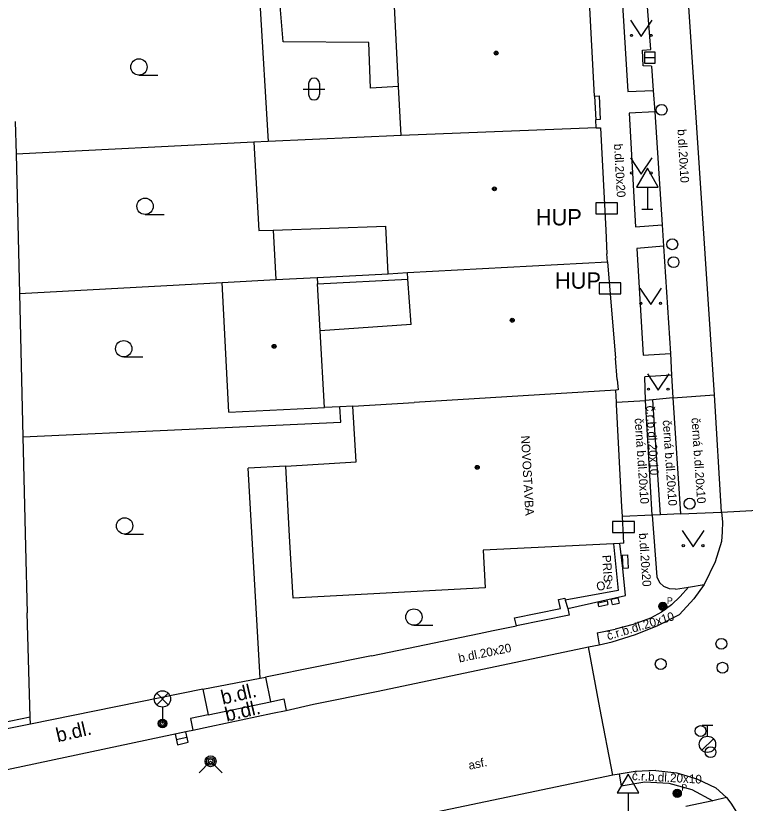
# Model space of a CAD drawing. Extents: x -596229 to -595156, y -1161237 to -1159376.
# Drawn here: x -595654.4 to -595620.89, y -1160970.18 to -1160933.99 of the extents above; entities that cross this region are included whole.
import ezdxf

# ---------------------------------------------------------------- set-up
doc = ezdxf.new("R2010")
doc.units = 0
for name, color, linetype in [('DOP - kresba z DSPS bez souradnic', 7, 'Continuous'), ('DOP - rozhrani ploch obecne', 7, 'Continuous'), ('Level 24', 7, 'Continuous'), ('Level 27', 7, 'Continuous'), ('Level 28', 7, 'Continuous'), ('Level 31', 7, 'Continuous'), ('Level 33', 7, 'Continuous'), ('Level 34', 7, 'Continuous'), ('Level 36', 7, 'Continuous'), ('Level 39', 7, 'Continuous'), ('silnoproud - povrch.  znaky a  RIS  skut. velikost', 7, 'Continuous'), ('slaboproud - povrch.  znaky a tel. budka skut. velikost', 7, 'Continuous'), ('TM - budovy zdene_ betonove - VP', 7, 'Continuous'), ('TM - chodniky - VP', 7, 'Continuous'), ('TM - komunikace - VP', 7, 'Continuous'), ('TM - letecke snimky - pomocna linie', 7, 'Continuous'), ('TM - plot drateny_ kovovy - VP', 7, 'Continuous'), ('TM - plot zdeny_ ohradni zed - VP', 7, 'Continuous'), ('TM - podezdivka plotu - VP', 7, 'Continuous'), ('TM - popis objektu', 7, 'Continuous'), ('TM - popis povrchu', 7, 'Continuous'), ('TM - rozhrani mezi zpev. plochami mezi sebou - VP', 7, 'Continuous'), ('TM - rozhrani ploch obecne - VP', 7, 'Continuous'), ('TM - vjezd na pozemek', 7, 'Continuous'), ('TM - vstup do budovy - zdene_ betonove', 7, 'Continuous'), ('Vrstva 34', 7, 'Continuous')]:
    doc.layers.add(name, color=color, linetype=linetype)

msp = doc.modelspace()

# ---------------------------------------------------------------- linework, layer by layer
at = {"layer": 'DOP - kresba z DSPS bez souradnic'}
for points in [[(-595642.11, -1160935.19), (-595642.27, -1160933.34)], [(-595638.18, -1160935.21), (-595642.11, -1160935.19)], [(-595638.1, -1160937.31), (-595638.18, -1160935.21)], [(-595636.82, -1160937.24), (-595638.1, -1160937.31)], [(-595640.53, -1160946.31), (-595636.38, -1160946.09)]]:
    msp.add_lwpolyline(points, dxfattribs=at)
at = {"layer": 'DOP - rozhrani ploch obecne'}
for points in [[(-595643.18, -1160933.39), (-595642.81, -1160939.77)], [(-595654.42, -1160938.84), (-595654.38, -1160940.34)], [(-595643.46, -1160939.8), (-595654.38, -1160940.34)], [(-595654.38, -1160940.34), (-595654.23, -1160946.75)], [(-595642.58, -1160943.84), (-595642.45, -1160946.11)], [(-595640.55, -1160946.01), (-595637.29, -1160945.84)], [(-595654.23, -1160946.75), (-595644.91, -1160946.24)], [(-595654.23, -1160946.75), (-595654.07, -1160953.34)], [(-595639.47, -1160952.66), (-595639.51, -1160951.96)], [(-595654.07, -1160953.34), (-595639.47, -1160952.66)], [(-595654.07, -1160953.34), (-595653.95, -1160958.4)], [(-595653.95, -1160958.4), (-595653.87, -1160961.43)]]:
    msp.add_lwpolyline(points, dxfattribs=at)
at = {"layer": 'Level 24'}
for points in [[(-595627.748, -1160943.089), (-595626.748, -1160943.089), (-595626.748, -1160942.589), (-595627.748, -1160942.589)], [(-595627.598, -1160946.759), (-595626.598, -1160946.759), (-595626.598, -1160946.259), (-595627.598, -1160946.259)], [(-595626.978, -1160957.729), (-595625.978, -1160957.729), (-595625.978, -1160957.229), (-595626.978, -1160957.229)]]:
    msp.add_lwpolyline(points, close=True, dxfattribs=at)
at = {"layer": 'Level 27'}
for p, q in [((-595625.52, -1160935.91), (-595625.02, -1160935.91)), ((-595647.024, -1160967.246), (-595646.536, -1160967.134))]:
    msp.add_line(p, q, dxfattribs=at)
for points in [[(-595625.52, -1160936.16), (-595625.02, -1160936.16), (-595625.02, -1160935.66), (-595625.52, -1160935.66)], [(-595646.967, -1160967.49), (-595646.48, -1160967.377), (-595646.593, -1160966.89), (-595647.08, -1160967.003)]]:
    msp.add_lwpolyline(points, close=True, dxfattribs=at)
at = {"layer": 'Level 28'}
for p, q in [((-595622.87, -1160966.595), (-595622.37, -1160966.595)), ((-595622.62, -1160967.095), (-595622.62, -1160966.595)), ((-595622.878, -1160967.742), (-595622.348, -1160967.212))]:
    msp.add_line(p, q, dxfattribs=at)
for centre, radius in [((-595624.73, -1160938.31), 0.25), ((-595624.24, -1160944.49), 0.25), ((-595624.18, -1160945.31), 0.25), ((-595623.44, -1160956.41), 0.25), ((-595622.94, -1160966.86), 0.25), ((-595622.62, -1160967.47), 0.375), ((-595622.48, -1160967.83), 0.25)]:
    msp.add_circle(centre, radius, dxfattribs=at)
at = {"layer": 'Level 31'}
msp.add_lwpolyline([(-595645.98, -1160968.78), (-595645.45, -1160968.25), (-595644.92, -1160968.78)], dxfattribs=at)
for centre, radius in [((-595621.98, -1160962.85), 0.25), ((-595624.77, -1160963.78), 0.25), ((-595621.93, -1160963.95), 0.25), ((-595645.45, -1160968.25), 0.25), ((-595645.45, -1160968.25), 0.18), ((-595645.45, -1160968.25), 0.11)]:
    msp.add_circle(centre, radius, dxfattribs=at)
at = {"layer": 'Level 33'}
for p, q in [((-595647.925, -1160965.65), (-595647.395, -1160965.12)), ((-595647.925, -1160965.12), (-595647.395, -1160965.65)), ((-595647.66, -1160965.76), (-595647.66, -1160966.51))]:
    msp.add_line(p, q, dxfattribs=at)
for centre, radius in [((-595647.66, -1160965.385), 0.375), ((-595647.66, -1160966.51), 0.2), ((-595647.66, -1160966.51), 0.145), ((-595647.66, -1160966.51), 0.0876)]:
    msp.add_circle(centre, radius, dxfattribs=at)
at = {"layer": 'Level 34'}
for p, q in [((-595625.38, -1160941.862), (-595625.38, -1160942.88)), ((-595625.63, -1160942.88), (-595625.13, -1160942.88)), ((-595626.27, -1160969.702), (-595626.27, -1160970.72))]:
    msp.add_line(p, q, dxfattribs=at)
for points in [[(-595625.88, -1160941.862), (-595624.88, -1160941.862), (-595625.38, -1160940.996)], [(-595626.77, -1160969.702), (-595625.77, -1160969.702), (-595626.27, -1160968.836)]]:
    msp.add_lwpolyline(points, close=True, dxfattribs=at)
at = {"layer": 'Level 36'}
for p, q in [((-595648.74, -1160936.715), (-595647.865, -1160936.715)), ((-595641.196, -1160937.356), (-595640.196, -1160937.356)), ((-595640.946, -1160937.106), (-595640.946, -1160937.606)), ((-595640.446, -1160937.106), (-595640.446, -1160937.606)), ((-595648.46, -1160943.115), (-595647.585, -1160943.115)), ((-595649.44, -1160949.665), (-595648.565, -1160949.665)), ((-595649.4, -1160957.805), (-595648.525, -1160957.805)), ((-595636.11, -1160961.995), (-595635.235, -1160961.995))]:
    msp.add_line(p, q, dxfattribs=at)
for points in [[(-595626.16, -1160934.19), (-595625.66, -1160934.94), (-595625.16, -1160934.19)], [(-595626.16, -1160940.51), (-595625.66, -1160941.26), (-595625.16, -1160940.51)], [(-595625.73, -1160946.5), (-595625.23, -1160947.25), (-595624.73, -1160946.5)], [(-595625.38, -1160950.45), (-595624.88, -1160951.2), (-595624.38, -1160950.45)], [(-595623.78, -1160957.64), (-595623.28, -1160958.39), (-595622.78, -1160957.64)]]:
    msp.add_lwpolyline(points, dxfattribs=at)
for centre, radius in [((-595626.11, -1160934.89), 0.05), ((-595625.211, -1160934.89), 0.05), ((-595648.74, -1160936.34), 0.375), ((-595626.11, -1160941.21), 0.05), ((-595625.211, -1160941.21), 0.05), ((-595648.46, -1160942.74), 0.375), ((-595625.68, -1160947.2), 0.05), ((-595624.781, -1160947.2), 0.05), ((-595649.44, -1160949.29), 0.375), ((-595625.33, -1160951.15), 0.05), ((-595624.431, -1160951.15), 0.05), ((-595649.4, -1160957.43), 0.375), ((-595623.73, -1160958.34), 0.05), ((-595622.831, -1160958.34), 0.05), ((-595636.11, -1160961.62), 0.375)]:
    msp.add_circle(centre, radius, dxfattribs=at)
for centre, start, end in [((-595640.696, -1160937.106), 0, 180), ((-595640.696, -1160937.606), 180, 0)]:
    msp.add_arc(centre, 0.25, start, end, dxfattribs=at)
at = {"layer": 'Level 39'}
for centre, radius in [((-595632.33, -1160935.7), 0.09), ((-595632.33, -1160935.7), 0.0398), ((-595632.41, -1160941.94), 0.09), ((-595632.41, -1160941.94), 0.0398), ((-595631.59, -1160947.98), 0.09), ((-595631.59, -1160947.98), 0.0398), ((-595642.53, -1160949.18), 0.09), ((-595642.53, -1160949.18), 0.0398), ((-595633.2, -1160954.74), 0.09), ((-595633.2, -1160954.74), 0.0398)]:
    msp.add_circle(centre, radius, dxfattribs=at)
at = {"layer": 'silnoproud - povrch.  znaky a  RIS  skut. velikost'}
for points in [[(-595626.54, -1160958.77), (-595626.29, -1160958.76)], [(-595626.29, -1160958.76), (-595626.26, -1160959.38)], [(-595626.54, -1160958.77), (-595626.51, -1160959.39)], [(-595626.26, -1160959.38), (-595626.51, -1160959.39)]]:
    msp.add_lwpolyline(points, dxfattribs=at)
at = {"layer": 'slaboproud - povrch.  znaky a tel. budka skut. velikost'}
for points in [[(-595627.65, -1160960.96), (-595627.23, -1160960.87)], [(-595627.23, -1160960.87), (-595627.2, -1160961.04)], [(-595627.04, -1160960.8), (-595626.74, -1160960.74)], [(-595626.98, -1160961.05), (-595627.04, -1160960.8)], [(-595626.74, -1160960.74), (-595626.68, -1160960.99)], [(-595627.61, -1160961.13), (-595627.65, -1160960.96)], [(-595627.61, -1160961.13), (-595627.2, -1160961.04)], [(-595626.98, -1160961.05), (-595626.68, -1160960.99)]]:
    msp.add_lwpolyline(points, dxfattribs=at)
at = {"layer": 'TM - budovy zdene_ betonove - VP'}
for points in [[(-595627.81, -1160937.68), (-595628.05, -1160933.02)], [(-595636.82, -1160937.24), (-595637.02, -1160933.22)], [(-595636.7, -1160939.49), (-595636.82, -1160937.24)], [(-595627.73, -1160939.14), (-595627.75, -1160938.77)], [(-595627.73, -1160939.14), (-595636.7, -1160939.49)], [(-595627.73, -1160939.14), (-595627.54, -1160939.13), (-595627.29, -1160943.84)], [(-595636.7, -1160939.49), (-595642.81, -1160939.77)], [(-595642.81, -1160939.77), (-595643.46, -1160939.8)], [(-595637.29, -1160945.84), (-595637.4, -1160943.66)], [(-595627.22, -1160945.3), (-595627.24, -1160944.92)], [(-595636.4, -1160945.79), (-595627.22, -1160945.3)], [(-595627.22, -1160945.3), (-595626.85, -1160949.72)], [(-595642.45, -1160946.11), (-595640.55, -1160946.01)], [(-595640.55, -1160946.01), (-595640.53, -1160946.31)], [(-595637.29, -1160945.84), (-595636.4, -1160945.79)], [(-595636.38, -1160946.09), (-595636.4, -1160945.79)], [(-595636.24, -1160948.18), (-595636.38, -1160946.09)], [(-595644.91, -1160946.24), (-595642.45, -1160946.11)], [(-595644.61, -1160952.21), (-595644.91, -1160946.24)], [(-595640.41, -1160948.46), (-595640.53, -1160946.31)], [(-595636.24, -1160948.18), (-595640.41, -1160948.46)], [(-595640.21, -1160951.99), (-595640.41, -1160948.46)], [(-595626.77, -1160950.7), (-595626.73, -1160951.18), (-595626.83, -1160951.19)], [(-595626.83, -1160951.19), (-595636.09, -1160951.76)], [(-595626.8, -1160951.74), (-595626.83, -1160951.19)], [(-595638.92, -1160951.93), (-595636.09, -1160951.76)], [(-595626.8, -1160951.85), (-595626.8, -1160951.74)], [(-595644.61, -1160952.21), (-595640.21, -1160951.99)], [(-595639.51, -1160951.96), (-595640.21, -1160951.99)], [(-595638.92, -1160951.93), (-595639.51, -1160951.96)], [(-595638.76, -1160954.49), (-595638.92, -1160951.93)], [(-595641.99, -1160954.68), (-595638.76, -1160954.49)], [(-595641.82, -1160957.9), (-595641.99, -1160954.68)], [(-595626.53, -1160957), (-595626.55, -1160956.56)], [(-595626.46, -1160958.23), (-595626.53, -1160957)], [(-595641.66, -1160960.75), (-595641.82, -1160957.9)], [(-595626.94, -1160958.25), (-595632.93, -1160958.55)], [(-595626.64, -1160958.24), (-595626.94, -1160958.25)], [(-595626.46, -1160958.23), (-595626.64, -1160958.24)], [(-595632.93, -1160958.55), (-595632.83, -1160960.28)], [(-595632.83, -1160960.28), (-595641.66, -1160960.75)]]:
    msp.add_lwpolyline(points, dxfattribs=at)
at = {"layer": 'TM - chodniky - VP'}
for points in [[(-595626.58, -1160932.48), (-595626.28, -1160937.46)], [(-595626.28, -1160937.46), (-595625.11, -1160937.42)], [(-595625.04, -1160938.4), (-595626.22, -1160938.46)], [(-595626.22, -1160938.46), (-595625.92, -1160943.69)], [(-595625.92, -1160943.69), (-595624.7, -1160943.6)], [(-595624.64, -1160944.58), (-595625.87, -1160944.68)], [(-595625.87, -1160944.68), (-595625.58, -1160949.59)], [(-595625.58, -1160949.59), (-595624.32, -1160949.51)], [(-595624.27, -1160950.51), (-595625.5, -1160950.58)], [(-595625.47, -1160951.67), (-595625.5, -1160950.58)], [(-595625.13, -1160951.63), (-595625.47, -1160951.67)], [(-595624.21, -1160951.54), (-595625.13, -1160951.63)], [(-595624.78, -1160956.92), (-595625.16, -1160956.94)], [(-595625.16, -1160956.94), (-595624.95, -1160959.77)], [(-595623.86, -1160956.87), (-595624.78, -1160956.92)], [(-595623.86, -1160956.87), (-595621.97, -1160956.8)], [(-595624.95, -1160959.77), (-595624.83, -1160960.03)], [(-595624.83, -1160960.03), (-595624.63, -1160960.22)], [(-595623.49, -1160960.25), (-595622.78, -1160960.13)], [(-595624.09, -1160960.34), (-595624.37, -1160960.33), (-595624.63, -1160960.22)], [(-595624.09, -1160960.34), (-595623.49, -1160960.25)], [(-595621.75, -1160969.92), (-595622.38, -1160970.07)], [(-595622.38, -1160970.07), (-595623.62, -1160970.33)]]:
    msp.add_lwpolyline(points, dxfattribs=at)
at = {"layer": 'TM - komunikace - VP'}
for points in [[(-595625.22, -1160935.53), (-595625.47, -1160932.39)], [(-595625.6, -1160935.56), (-595625.22, -1160935.53)], [(-595625.19, -1160936.31), (-595625.57, -1160936.29), (-595625.6, -1160935.56)], [(-595625.19, -1160936.31), (-595625.11, -1160937.42)], [(-595625.11, -1160937.42), (-595625.04, -1160938.4)], [(-595625.04, -1160938.4), (-595624.7, -1160943.6)], [(-595624.7, -1160943.6), (-595624.64, -1160944.58)], [(-595624.64, -1160944.58), (-595624.32, -1160949.51)], [(-595624.32, -1160949.51), (-595624.27, -1160950.51)], [(-595624.27, -1160950.51), (-595624.21, -1160951.54)], [(-595624.21, -1160951.54), (-595622.3, -1160951.41)], [(-595621.97, -1160956.8), (-595622.3, -1160951.41)], [(-595621.97, -1160956.8), (-595621.93, -1160957.25), (-595621.94, -1160957.7), (-595621.98, -1160958.15)], [(-595621.98, -1160958.15), (-595622.26, -1160959.09), (-595622.78, -1160960.13)], [(-595622.78, -1160960.13), (-595623.24, -1160960.79), (-595623.9, -1160961.5)], [(-595624.9, -1160962.01), (-595623.9, -1160961.5)], [(-595627.6, -1160962.89), (-595627, -1160962.76), (-595625.93, -1160962.43), (-595624.9, -1160962.01)], [(-595637.75, -1160965.02), (-595628.09, -1160962.99)], [(-595628.09, -1160962.99), (-595627.6, -1160962.89)], [(-595641.98, -1160965.91), (-595640.72, -1160965.63), (-595637.75, -1160965.02)], [(-595646.26, -1160966.82), (-595645.48, -1160966.65), (-595642.61, -1160966.04), (-595641.98, -1160965.91)], [(-595655.32, -1160968.73), (-595646.51, -1160966.87), (-595646.26, -1160966.82)], [(-595626.97, -1160968.89), (-595636.69, -1160970.93)], [(-595626.68, -1160968.84), (-595626.97, -1160968.89)], [(-595625.95, -1160968.72), (-595626.68, -1160968.84)], [(-595624.99, -1160968.67), (-595625.95, -1160968.72)], [(-595624.99, -1160968.67), (-595624.03, -1160968.78), (-595623.11, -1160969.05), (-595622.24, -1160969.47)], [(-595622.24, -1160969.47), (-595621.75, -1160969.92)], [(-595621.75, -1160969.92), (-595621.55, -1160970.17), (-595621.29, -1160970.59)]]:
    msp.add_lwpolyline(points, dxfattribs=at)
at = {"layer": 'TM - letecke snimky - pomocna linie'}
for points in [[(-595643.46, -1160939.8), (-595643.24, -1160943.86), (-595642.58, -1160943.84)], [(-595642.58, -1160943.84), (-595637.4, -1160943.66)], [(-595641.99, -1160954.68), (-595643.72, -1160954.78)], [(-595643.17, -1160964.43), (-595643.72, -1160954.78)]]:
    msp.add_lwpolyline(points, dxfattribs=at)
at = {"layer": 'TM - plot drateny_ kovovy - VP'}
for points in [[(-595653.74, -1160966.22), (-595653.87, -1160961.43)], [(-595638.06, -1160963.4), (-595633.11, -1160962.38)], [(-595638.06, -1160963.4), (-595642.93, -1160964.38)], [(-595645.8, -1160964.94), (-595653.73, -1160966.55)], [(-595653.74, -1160966.22), (-595656.42, -1160966.78), (-595656.35, -1160967.07)], [(-595653.73, -1160966.55), (-595653.74, -1160966.22)]]:
    msp.add_lwpolyline(points, dxfattribs=at)
at = {"layer": 'TM - plot zdeny_ ohradni zed - VP'}
for points in [[(-595626.94, -1160958.25), (-595626.73, -1160960.4), (-595629.16, -1160960.84)], [(-595631.48, -1160961.66), (-595629.38, -1160961.23), (-595629.47, -1160960.82)], [(-595633.11, -1160962.38), (-595632.46, -1160962.24)]]:
    msp.add_lwpolyline(points, dxfattribs=at)
at = {"layer": 'TM - podezdivka plotu - VP'}
for points in [[(-595626.51, -1160959.39), (-595626.64, -1160958.24)], [(-595626.38, -1160960.63), (-595626.51, -1160959.39)], [(-595629.47, -1160960.82), (-595629.18, -1160960.75)], [(-595629.18, -1160960.75), (-595629.16, -1160960.84)], [(-595629.16, -1160960.84), (-595629.04, -1160961.22)], [(-595629.04, -1160961.22), (-595626.38, -1160960.63)], [(-595629.04, -1160961.22), (-595628.98, -1160961.53), (-595631.39, -1160962.02)], [(-595631.39, -1160962.02), (-595631.48, -1160961.66)], [(-595653.73, -1160966.55), (-595656.35, -1160967.07)]]:
    msp.add_lwpolyline(points, dxfattribs=at)
at = {"layer": 'TM - rozhrani mezi zpev. plochami mezi sebou - VP'}
for points in [[(-595626.8, -1160951.74), (-595625.47, -1160951.67)], [(-595625.16, -1160956.94), (-595625.47, -1160951.67)], [(-595624.78, -1160956.92), (-595625.13, -1160951.63)], [(-595624.21, -1160951.54), (-595623.86, -1160956.87)], [(-595625.16, -1160956.94), (-595626.53, -1160957)], [(-595623.49, -1160960.25), (-595623.87, -1160960.68), (-595624.28, -1160961.06), (-595624.74, -1160961.39), (-595625.24, -1160961.67)], [(-595625.24, -1160961.67), (-595626.04, -1160961.96), (-595626.86, -1160962.18)], [(-595627.69, -1160962.35), (-595626.86, -1160962.18)], [(-595627.69, -1160962.35), (-595627.6, -1160962.89)], [(-595626.68, -1160968.84), (-595626.59, -1160969.38)], [(-595626.59, -1160969.38), (-595625.5, -1160969.19)], [(-595625.5, -1160969.19), (-595624.4, -1160969.25), (-595623.34, -1160969.54), (-595622.38, -1160970.07)]]:
    msp.add_lwpolyline(points, dxfattribs=at)
at = {"layer": 'TM - rozhrani ploch obecne - VP'}
for points in [[(-595622.3, -1160951.41), (-595623.54, -1160932.63), (-595624.85, -1160913.55), (-595625.46, -1160904.3)], [(-595627.81, -1160937.68), (-595627.59, -1160937.67), (-595627.55, -1160938.76), (-595627.75, -1160938.77)], [(-595621.97, -1160956.8), (-595620.01, -1160956.69), (-595617.86, -1160956.57)], [(-595626.97, -1160968.89), (-595627.56, -1160965.8), (-595628.09, -1160962.99)], [(-595642.93, -1160964.38), (-595642.69, -1160965.51)], [(-595645.8, -1160964.94), (-595645.56, -1160966.11)], [(-595645.56, -1160966.11), (-595642.69, -1160965.51)], [(-595642.69, -1160965.51), (-595642.09, -1160965.38), (-595641.98, -1160965.91)], [(-595645.56, -1160966.11), (-595646.37, -1160966.28), (-595646.26, -1160966.82)]]:
    msp.add_lwpolyline(points, dxfattribs=at)
at = {"layer": 'TM - vjezd na pozemek'}
for points in [[(-595632.46, -1160962.24), (-595631.39, -1160962.02)], [(-595645.8, -1160964.94), (-595643.17, -1160964.43)], [(-595643.17, -1160964.43), (-595642.93, -1160964.38)]]:
    msp.add_lwpolyline(points, dxfattribs=at)
at = {"layer": 'TM - vstup do budovy - zdene_ betonove'}
for points in [[(-595627.81, -1160937.68), (-595627.75, -1160938.77)], [(-595627.29, -1160943.84), (-595627.24, -1160944.92)], [(-595626.77, -1160950.7), (-595626.85, -1160949.72)], [(-595626.55, -1160956.56), (-595626.8, -1160951.85)]]:
    msp.add_lwpolyline(points, dxfattribs=at)
at = {"layer": 'Vrstva 34'}
for centre, radius in [((-595624.67, -1160961.13), 0.188), ((-595624.67, -1160961.13), 0.15), ((-595624.67, -1160961.13), 0.113), ((-595624.67, -1160961.13), 0.075), ((-595624.67, -1160961.13), 0.0375), ((-595624.01, -1160969.72), 0.188), ((-595624.01, -1160969.72), 0.15), ((-595624.01, -1160969.72), 0.113), ((-595624.01, -1160969.72), 0.075), ((-595624.01, -1160969.72), 0.0375)]:
    msp.add_circle(centre, radius, dxfattribs=at)

# ---------------------------------------------------------------- texts
at = {"layer": 'TM - popis objektu'}
for p in [(-595630.51, -1160943.62), (-595629.63, -1160946.53)]:
    msp.add_text('HUP', height=0.75, dxfattribs=at).set_placement(p)
for s, rotation, p in [('NOVOSTAVBA', 273.1663, (-595631.19, -1160953.29)), ('PRIS', 273.7723, (-595627.46, -1160958.78)), ('O2', 12.1549, (-595627.68, -1160960.43))]:
    msp.add_text(s, height=0.4, rotation=rotation, dxfattribs=at).set_placement(p)
at = {"layer": 'TM - popis povrchu'}
for s, height, rotation, p in [('b.dl.20x10', 0.4, 273.3074, (-595624, -1160939.21)), ('b.dl.20x20', 0.4, 273.3074, (-595626.92, -1160939.88)), ('č.r.b.dl.20x10', 0.39998, 273.3074, (-595625.44, -1160951.91)), ('černá b.dl.20x10', 0.39998, 273.9204, (-595625.97, -1160952.49)), ('černá b.dl.20x10', 0.39998, 273.9204, (-595624.68, -1160952.58)), ('černá b.dl.20x10', 0.39998, 273.9204, (-595623.36, -1160952.47)), ('b.dl.20x20', 0.4, 274, (-595625.77, -1160957.77)), ('č.r.b.dl.20x10', 0.39998, 17, (-595627.18, -1160962.69)), ('b.dl.20x20', 0.4, 11.5932, (-595634.02, -1160963.71)), ('b.dl.', 0.65, 13.11, (-595644.89, -1160965.65)), ('b.dl.', 0.65, 13.11, (-595644.71, -1160966.43)), ('b.dl.', 0.65, 13.11, (-595652.47, -1160967.38)), ('asf.', 0.4, 11.5932, (-595633.56, -1160968.64)), ('č.r.b.dl.20x10', 0.39998, 357, (-595626.1, -1160969.11))]:
    msp.add_text(s, height=height, rotation=rotation, dxfattribs=at).set_placement(p)
at = {"layer": 'Vrstva 34'}
for p in [(-595624.482, -1160961.017), (-595623.822, -1160969.607)]:
    msp.add_text('P', height=0.3, dxfattribs=at).set_placement(p)

doc.saveas('drawing.dxf')
